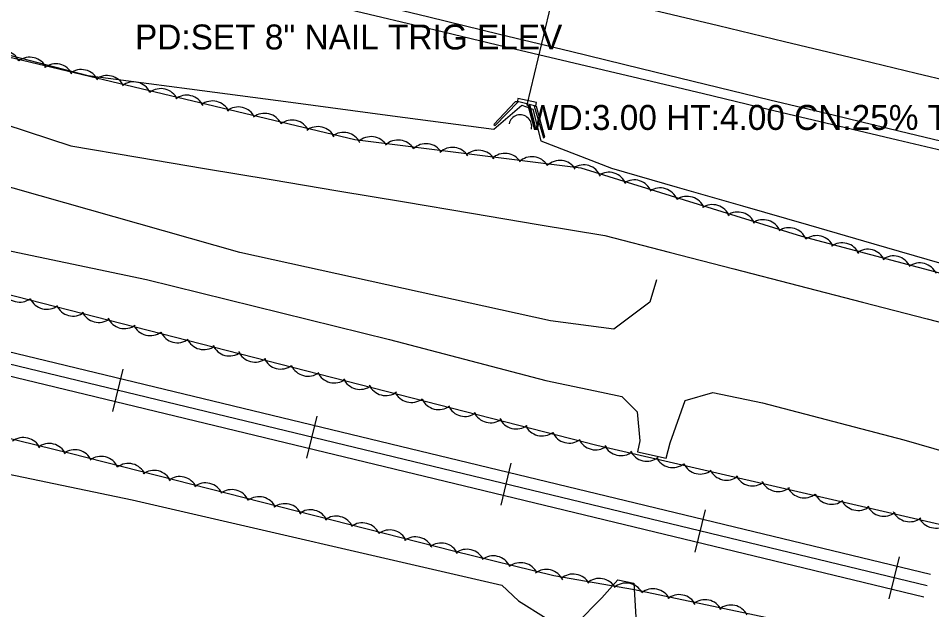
# Model space of a CAD drawing. Extents: x 1441650 to 1491889, y 345904 to 358319.
# Drawn here: x 1455015 to 1455198, y 352171.8 to 352290.3 of the extents above; entities that cross this region are included whole.
import ezdxf

# ---------------------------------------------------------------- set-up
doc = ezdxf.new("R2010")
doc.units = 0
for name, color, linetype in [('S_CROSS_DRAIN', 7, 'Continuous'), ('S_CROSS_DRAIN_ANNOT', 7, 'Continuous'), ('S_DITCHLINE', 7, 'Continuous'), ('S_DRG_PT_SYM', 7, 'Continuous'), ('S_EDGE_PAVEMENT', 7, 'Continuous'), ('S_HEADWALL', 7, 'Continuous'), ('S_PAVEMENT_CROWN', 7, 'Continuous'), ('S_RAILROAD', 7, 'Continuous'), ('S_SECONDARY_CTL_ANNOT', 7, 'Continuous'), ('S_SHOULDER', 7, 'Continuous'), ('S_STREAM', 7, 'Continuous'), ('S_TREE', 7, 'Continuous'), ('S_WALL', 7, 'Continuous')]:
    doc.layers.add(name, color=color, linetype=linetype)

msp = doc.modelspace()

# ---------------------------------------------------------------- linework, layer by layer
at = {"layer": 'S_CROSS_DRAIN'}
msp.add_line((1455116.96, 352272.93), (1455128.68, 352321.85), dxfattribs=at)
msp.add_arc((1455115.59, 352268.65), 2.3, 346.2718, 166.601, dxfattribs=at)
at = {"layer": 'S_DITCHLINE'}
for points in [[(1455002.2, 352285.77), (1455015.59, 352282.31), (1455028.98, 352278.84), (1455049.32, 352276.15), (1455069.66, 352273.46), (1455090, 352270.77), (1455110.33, 352268.08), (1455115.92, 352272.87), (1455118.09, 352272.12), (1455119.7, 352265.75), (1455133.85, 352260.29), (1455147, 352256.49), (1455160.15, 352252.7), (1455173.31, 352248.91), (1455186.46, 352245.11), (1455199.61, 352241.32), (1455212.77, 352237.52), (1455225.92, 352233.73), (1455239.07, 352229.94), (1455256.24, 352225.69), (1455273.4, 352221.43)], [(1455012.37, 352269.11), (1455025.59, 352264.71), (1455038.96, 352262.46), (1455052.33, 352260.22), (1455065.7, 352257.98), (1455079.07, 352255.74), (1455092.44, 352253.5), (1455105.82, 352251.25), (1455119.19, 352249.01), (1455132.56, 352246.77), (1455145.46, 352243.44), (1455158.37, 352240.1), (1455171.28, 352236.77), (1455184.19, 352233.44), (1455197.1, 352230.11), (1455210, 352226.77), (1455222.91, 352223.44), (1455235.82, 352220.11), (1455257.12, 352215.83), (1455278.43, 352211.54)]]:
    msp.add_lwpolyline(points, dxfattribs=at)
at = {"layer": 'S_DRG_PT_SYM'}
msp.add_lwpolyline([(1455116.96, 352272.93), (1455116.96, 352272.98), (1455116.96, 352272.93), (1455116.91, 352272.93), (1455116.96, 352272.93), (1455116.96, 352272.88), (1455116.96, 352272.93), (1455117.01, 352272.93)], dxfattribs=at)
at = {"layer": 'S_EDGE_PAVEMENT'}
msp.add_lwpolyline([(1455006.5, 352312.6), (1455020.87, 352309.1), (1455035.25, 352305.6), (1455059.19, 352299.83), (1455083.12, 352294.05), (1455097.3, 352290.6), (1455111.47, 352287.14), (1455125.65, 352283.69), (1455139.82, 352280.23), (1455152.72, 352277.11), (1455165.62, 352273.99), (1455178.52, 352270.87), (1455191.42, 352267.76), (1455205.04, 352264.45), (1455218.66, 352261.14), (1455232.28, 352257.83), (1455245.9, 352254.52), (1455259.47, 352251.24), (1455273.04, 352247.95), (1455286.61, 352244.67), (1455300.18, 352241.39)], dxfattribs=at)
at = {"layer": 'S_HEADWALL'}
msp.add_lwpolyline([(1455115.11, 352274.22), (1455115.03, 352273.69), (1455118.73, 352272.75), (1455118.85, 352273.44)], close=True, dxfattribs=at)
at = {"layer": 'S_PAVEMENT_CROWN'}
msp.add_lwpolyline([(1455009.57, 352323.82), (1455024.03, 352320.26), (1455038.49, 352316.7), (1455062.19, 352311), (1455085.88, 352305.29), (1455099.93, 352301.97), (1455113.99, 352298.65), (1455128.04, 352295.33), (1455142.09, 352292.02), (1455155.29, 352288.85), (1455168.5, 352285.67), (1455181.7, 352282.5), (1455194.9, 352279.33), (1455208.4, 352276.12), (1455221.9, 352272.9), (1455235.4, 352269.69), (1455248.9, 352266.47), (1455262.58, 352263.22), (1455276.26, 352259.96), (1455289.94, 352256.7), (1455303.63, 352253.44)], dxfattribs=at)
at = {"layer": 'S_RAILROAD'}
for p, q in [((1455033.99, 352211.54), (1455036.03, 352219.97)), ((1455035.56, 352218.02), (1455035.53, 352217.92)), ((1455034.45, 352213.44), (1455034.46, 352213.48)), ((1455072.88, 352202.14), (1455074.91, 352210.57)), ((1455074.44, 352208.63), (1455074.42, 352208.53)), ((1455073.34, 352204.05), (1455073.35, 352204.09)), ((1455111.76, 352192.75), (1455113.8, 352201.18)), ((1455113.33, 352199.24), (1455113.3, 352199.13)), ((1455112.22, 352194.66), (1455112.23, 352194.69)), ((1455150.64, 352183.36), (1455152.68, 352191.79)), ((1455152.21, 352189.84), (1455152.19, 352189.74)), ((1455151.1, 352185.26), (1455151.11, 352185.3)), ((1455189.53, 352173.96), (1455191.56, 352182.39)), ((1455191.09, 352180.45), (1455191.07, 352180.35)), ((1455189.99, 352175.87), (1455190, 352175.91))]:
    msp.add_line(p, q, dxfattribs=at)
for points in [[(1455197.77, 352178.84), (1454833.57, 352266.82)], [(1455197.11, 352176.59), (1454833.02, 352264.55)], [(1455196.44, 352174.31), (1454832.46, 352262.24)], [(1455035.04, 352215.74), (1455035.01, 352215.75)], [(1455073.92, 352206.35), (1455073.89, 352206.36)], [(1455112.81, 352196.96), (1455112.78, 352196.96)], [(1455151.69, 352187.56), (1455151.66, 352187.57)], [(1455190.57, 352178.17), (1455190.55, 352178.18)]]:
    msp.add_lwpolyline(points, dxfattribs=at)
at = {"layer": 'S_SHOULDER'}
msp.add_lwpolyline([(1455005.94, 352310.35), (1455020.41, 352306.83), (1455034.87, 352303.32), (1455058.82, 352297.51), (1455082.77, 352291.7), (1455096.91, 352288.35), (1455111.05, 352284.99), (1455125.19, 352281.64), (1455139.33, 352278.28), (1455152.28, 352275.2), (1455165.24, 352272.11), (1455178.2, 352269.03), (1455191.15, 352265.94), (1455204.77, 352262.71), (1455218.39, 352259.48), (1455232, 352256.25), (1455245.62, 352253.02), (1455259.09, 352249.71), (1455272.56, 352246.41), (1455286.04, 352243.1), (1455299.51, 352239.79)], dxfattribs=at)
at = {"layer": 'S_STREAM'}
for points in [[(1455142.91, 352237.91), (1455141.54, 352233.39), (1455134.36, 352227.99), (1455121.63, 352229.7), (1455059.44, 352243.37), (1455004.1, 352259.04)], [(1454981.16, 352250.46), (1455040.76, 352237.99), (1455089.39, 352225.96), (1455120.7, 352217.7), (1455131.85, 352215.39), (1455135.96, 352214.51), (1455139.01, 352211.43), (1455139.53, 352205.62), (1455139.09, 352203.46), (1455144.82, 352202.15), (1455145.66, 352205.26), (1455148.66, 352213.74), (1455154.17, 352215.3), (1455164.11, 352213.25), (1455192.45, 352205.83), (1455268, 352184.01)], [(1454992.68, 352203.26), (1455037.86, 352193.79), (1455111.93, 352176.7), (1455115.24, 352173.57), (1455120.78, 352170.08)], [(1455126.81, 352169), (1455131.95, 352174.2), (1455135.12, 352177.78), (1455138.33, 352177.12), (1455138.81, 352169.15)]]:
    msp.add_lwpolyline(points, dxfattribs=at)
at = {"layer": 'S_TREE'}
for points in [[(1454962.69, 352294.69), (1455082.43, 352265.99), (1455127.73, 352260.33), (1455171.95, 352246.67), (1455237.79, 352229.12), (1455266.56, 352215.9), (1455276.91, 352188.42), (1455269.69, 352172.72), (1455130.94, 352204.71), (1454988.1, 352241.29), (1454883.15, 352265.69), (1454742.86, 352299.41), (1454579.09, 352337.35), (1454448.11, 352370.53)], [(1454720.16, 352277.33), (1454872.99, 352241.33), (1454943.73, 352222.23), (1454977.97, 352214.82), (1455025.42, 352203.17), (1455102.25, 352183.63), (1455122.31, 352178.67), (1455138.5, 352175.87), (1455168.52, 352169.53), (1455253.06, 352148.2), (1455262.5, 352142.36), (1455264.98, 352131.4), (1455261.62, 352116.37)]]:
    msp.add_lwpolyline(points, dxfattribs=at)
for centre, major_axis, ratio, start_param, end_param in [((1455011.87, 352280.2), (-3.54, 0.85), 0.999998, 3.825789, 5.598989), ((1455017.35, 352278.86), (-3.54, 0.85), 0.999998, 3.825788, 5.598989), ((1455022.52, 352277.54), (-3.54, 0.85), 0.999998, 3.825788, 5.598989), ((1455027.67, 352276.38), (-3.54, 0.85), 0.999998, 3.825788, 5.598989), ((1455032.84, 352275.18), (-3.54, 0.85), 0.999998, 3.825789, 5.598989), ((1455038.13, 352273.91), (-3.54, 0.85), 0.999998, 3.825789, 5.598989), ((1455043.61, 352272.56), (-3.54, 0.85), 0.999998, 3.825788, 5.598989), ((1455048.78, 352271.25), (-3.54, 0.85), 0.999998, 3.825788, 5.598989), ((1455053.94, 352270.09), (-3.54, 0.85), 0.999998, 3.825788, 5.598989), ((1455059.1, 352268.89), (-3.54, 0.85), 0.999998, 3.825789, 5.598989), ((1455064.4, 352267.61), (-3.54, 0.85), 0.999998, 3.825789, 5.598989), ((1455069.88, 352266.27), (-3.54, 0.85), 0.999998, 3.825788, 5.598989), ((1455075.05, 352264.95), (-3.54, 0.85), 0.999998, 3.825788, 5.598989), ((1455080.2, 352263.79), (-3.54, 0.85), 0.999998, 3.825788, 5.598989), ((1455085.73, 352262.94), (-0.95, 3.52), 0.999984, 5.007008, 6.780208), ((1455091.13, 352262.26), (-0.95, 3.52), 0.999984, 5.007008, 6.780208), ((1455096.72, 352261.52), (-0.95, 3.52), 0.999984, 5.007008, 6.780208), ((1455102.01, 352260.79), (-0.95, 3.52), 0.999984, 5.007008, 6.780208), ((1455107.26, 352260.21), (-0.95, 3.52), 0.999984, 5.007008, 6.780208), ((1455112.53, 352259.58), (-0.95, 3.52), 0.999984, 5.007008, 6.780208), ((1455117.93, 352258.91), (-0.95, 3.52), 0.999984, 5.007008, 6.780208), ((1455123.52, 352258.17), (-0.95, 3.52), 0.999984, 5.007008, 6.780208), ((1455128.29, 352257.29), (-3.48, 1.08), 0.999998, 3.825788, 5.598989), ((1455133.36, 352255.81), (-3.48, 1.08), 0.999998, 3.825788, 5.598989), ((1455138.44, 352254.27), (-3.48, 1.08), 0.999998, 3.825789, 5.598989), ((1455143.63, 352252.67), (-3.48, 1.08), 0.999998, 3.825789, 5.598989), ((1455149.02, 352250.97), (-3.48, 1.08), 0.999998, 3.825788, 5.598989), ((1455154.09, 352249.32), (-3.48, 1.08), 0.999998, 3.825788, 5.598989), ((1455159.16, 352247.83), (-3.48, 1.08), 0.999998, 3.825788, 5.598989), ((1455164.24, 352246.3), (-3.48, 1.08), 0.999998, 3.825789, 5.598989), ((1455169.44, 352244.69), (-3.48, 1.08), 0.999998, 3.825789, 5.598989), ((1455174.97, 352243.11), (-3.25, 1.64), 0.999998, 4.033493, 5.806694), ((1455180.1, 352241.67), (-3.25, 1.64), 0.999998, 4.033493, 5.806694), ((1455185.22, 352240.38), (-3.25, 1.64), 0.999998, 4.033493, 5.806694), ((1455190.36, 352239.05), (-3.25, 1.64), 0.999998, 4.033494, 5.806694), ((1455195.62, 352237.64), (-3.25, 1.64), 0.999998, 4.033494, 5.806694), ((1455015.3, 352237.07), (3.45, 1.18), 0.999997, 3.244585, 5.017786), ((1455020.77, 352235.64), (3.45, 1.18), 0.999997, 3.244586, 5.017786), ((1455026.04, 352234.28), (3.45, 1.18), 0.999997, 3.244586, 5.017786), ((1455031.18, 352233), (3.45, 1.18), 0.999997, 3.244585, 5.017786), ((1455036.32, 352231.76), (3.45, 1.18), 0.999997, 3.244585, 5.017786), ((1455041.47, 352230.37), (3.45, 1.18), 0.999997, 3.244585, 5.017786), ((1455046.93, 352228.94), (3.45, 1.18), 0.999997, 3.244586, 5.017786), ((1455052.2, 352227.58), (3.45, 1.18), 0.999997, 3.244586, 5.017786), ((1455057.35, 352226.3), (3.45, 1.18), 0.999997, 3.244585, 5.017786), ((1455062.48, 352225.06), (3.45, 1.18), 0.999997, 3.244585, 5.017786), ((1455067.63, 352223.67), (3.45, 1.18), 0.999997, 3.244585, 5.017786), ((1455073.09, 352222.24), (3.45, 1.18), 0.999997, 3.244586, 5.017786), ((1455078.36, 352220.88), (3.45, 1.18), 0.999997, 3.244586, 5.017786), ((1455083.51, 352219.6), (3.45, 1.18), 0.999997, 3.244585, 5.017786), ((1455088.65, 352218.36), (3.45, 1.18), 0.999997, 3.244585, 5.017786), ((1455093.8, 352216.97), (3.45, 1.18), 0.999997, 3.244585, 5.017786), ((1455099.26, 352215.54), (3.45, 1.18), 0.999997, 3.244586, 5.017786), ((1455104.53, 352214.18), (3.45, 1.18), 0.999997, 3.244586, 5.017786), ((1455109.68, 352212.9), (3.45, 1.18), 0.999997, 3.244585, 5.017786), ((1455114.81, 352211.66), (3.45, 1.18), 0.999997, 3.244585, 5.017786), ((1455119.96, 352210.27), (3.45, 1.18), 0.999997, 3.244585, 5.017786), ((1455125.42, 352208.84), (3.45, 1.18), 0.999997, 3.244586, 5.017786), ((1455016.07, 352202.65), (-2.38, 2.76), 0.999977, 4.445366, 6.218567), ((1455021.22, 352201.46), (-2.38, 2.76), 0.999977, 4.445366, 6.218567), ((1455130.69, 352207.48), (3.45, 1.18), 0.999997, 3.244586, 5.017786), ((1455135.8, 352206.32), (2.14, 2.95), 0.999985, 2.654993, 4.428194), ((1455026.36, 352200.22), (-3.53, 0.9), 0.999985, 3.825789, 5.598989), ((1455140.97, 352205.2), (2.14, 2.95), 0.999985, 2.654993, 4.428194), ((1455031.63, 352198.88), (-3.53, 0.9), 0.999985, 3.825789, 5.598989), ((1455037.09, 352197.46), (-3.53, 0.9), 0.999985, 3.825789, 5.598989), ((1455146.15, 352203.93), (2.14, 2.95), 0.999985, 2.654993, 4.428194), ((1455042.24, 352196.07), (-3.53, 0.9), 0.999985, 3.825789, 5.598989), ((1455151.64, 352202.63), (2.14, 2.95), 0.999985, 2.654993, 4.428194), ((1455156.94, 352201.41), (2.14, 2.95), 0.999985, 2.654993, 4.428194), ((1455047.38, 352194.84), (-3.53, 0.9), 0.999985, 3.825789, 5.598989), ((1455162.12, 352200.25), (2.14, 2.95), 0.999985, 2.654993, 4.428194), ((1455167.28, 352199.14), (2.14, 2.95), 0.999985, 2.654993, 4.428194), ((1455052.53, 352193.57), (-3.53, 0.9), 0.999985, 3.825789, 5.598989), ((1455057.8, 352192.22), (-3.53, 0.9), 0.999985, 3.825789, 5.598989), ((1455172.47, 352197.87), (2.14, 2.95), 0.999985, 2.654993, 4.428194), ((1455063.27, 352190.8), (-3.53, 0.9), 0.999985, 3.825789, 5.598989), ((1455177.96, 352196.57), (2.14, 2.95), 0.999985, 2.654993, 4.428194), ((1455183.26, 352195.34), (2.14, 2.95), 0.999985, 2.654993, 4.428194), ((1455068.42, 352189.41), (-3.53, 0.9), 0.999985, 3.825789, 5.598989), ((1455073.56, 352188.18), (-3.53, 0.9), 0.999985, 3.825789, 5.598989), ((1455188.44, 352194.18), (2.14, 2.95), 0.999985, 2.654993, 4.428194), ((1455078.71, 352186.91), (-3.53, 0.9), 0.999985, 3.825789, 5.598989), ((1455193.6, 352193.07), (2.14, 2.95), 0.999985, 2.654993, 4.428194), ((1455198.78, 352191.8), (2.14, 2.95), 0.999985, 2.654993, 4.428194), ((1455083.98, 352185.57), (-3.53, 0.9), 0.999985, 3.825789, 5.598989), ((1455089.44, 352184.14), (-3.53, 0.9), 0.999985, 3.825789, 5.598989), ((1455094.6, 352182.76), (-3.53, 0.9), 0.999985, 3.825789, 5.598989), ((1455099.73, 352181.53), (-3.53, 0.9), 0.999985, 3.825789, 5.598989), ((1455104.91, 352180.27), (-3.54, 0.87), 0.999985, 3.825789, 5.598989), ((1455110.19, 352178.96), (-3.54, 0.87), 0.999985, 3.825789, 5.598989), ((1455115.66, 352177.58), (-3.54, 0.87), 0.999985, 3.825789, 5.598989), ((1455120.82, 352176.23), (-3.54, 0.87), 0.999985, 3.825789, 5.598989), ((1455126.21, 352175.3), (-1.09, -3.48), 0.999084, 2.387889, 4.16109), ((1455131.44, 352174.43), (-1.09, -3.48), 0.999084, 2.387889, 4.16109), ((1455136.8, 352173.5), (-1.09, -3.48), 0.999084, 2.387889, 4.16109), ((1455142.23, 352172.36), (-3.44, 1.19), 0.999984, 3.950174, 5.723375), ((1455147.43, 352171.19), (-3.44, 1.19), 0.999984, 3.950174, 5.723375), ((1455152.61, 352170.17), (-3.44, 1.19), 0.999984, 3.950174, 5.723375), ((1455157.81, 352169.11), (-3.44, 1.19), 0.999984, 3.950174, 5.723375)]:
    msp.add_ellipse(centre, major_axis=major_axis, ratio=ratio, start_param=start_param, end_param=end_param, dxfattribs=at)
at = {"layer": 'S_WALL'}
for points in [[(1455114.55, 352273.58), (1455110.34, 352269.04), (1455110.56, 352268.84), (1455115.2, 352273.57)], [(1455118.84, 352272.6), (1455118.39, 352272.67), (1455120.24, 352266.36), (1455120.53, 352266.48)]]:
    msp.add_lwpolyline(points, close=True, dxfattribs=at)

# ---------------------------------------------------------------- texts
at = {"layer": 'S_CROSS_DRAIN_ANNOT'}
msp.add_text('WD:3.00 HT:4.00 CN:25% TY:RC BO', height=5, dxfattribs=at).set_placement((1455116.96, 352267.93))
at = {"layer": 'S_SECONDARY_CTL_ANNOT'}
msp.add_text('PD:SET 8" NAIL TRIG ELEV', height=5, dxfattribs=at).set_placement((1455038.43, 352284.05))

doc.saveas('drawing.dxf')
